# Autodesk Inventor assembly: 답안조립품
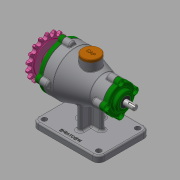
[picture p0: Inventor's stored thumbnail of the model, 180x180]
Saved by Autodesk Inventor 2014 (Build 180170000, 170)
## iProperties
Created: 2020-12
Part Number: 답안조립품
Document SubType Name: Assembly
Designer: kh
Author: kh
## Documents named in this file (14)
- C:\Users\kh\Desktop\701206V1030\답안조립품.iam
- C:\Users\kh\Desktop\701206V1030\본체.ipt
- C:\Users\kh\Desktop\701206V1030\개스킷 A.ipt
- C:\Users\kh\Desktop\701206V1030\개스킷 B.ipt
- C:\Users\kh\Desktop\701206V1030\앞커버.ipt
- C:\Users\kh\Desktop\701206V1030\뒤커버.ipt
- C:\Users\kh\Desktop\701206V1030\오일 실 17 30 8.ipt
- C:\Users\kh\Desktop\701206V1030\오일 실 10 20 7.ipt
- C:\Users\kh\Desktop\701206V1030\베어링 6203.ipt
- C:\Users\kh\Desktop\701206V1030\베어링 6200.ipt
- C:\Users\kh\Desktop\701206V1030\축.ipt
- C:\Users\kh\Desktop\701206V1030\키 4x4x14.ipt
- C:\Users\kh\Desktop\701206V1030\스프로킷.ipt
- C:\Users\kh\Desktop\701206V1030\마개.ipt
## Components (2 placed, 2 different names)
1. 개스킷 A:1
2. 개스킷 B:1
